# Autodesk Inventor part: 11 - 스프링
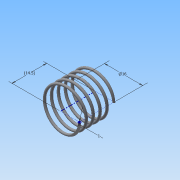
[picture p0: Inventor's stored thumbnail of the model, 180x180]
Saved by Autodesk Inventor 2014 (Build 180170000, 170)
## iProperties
Created: 2015-06
Part Number: 11 - 스프링
Material: 강철, 연강
Document SubType Name: Modeling
Designer: Administrator
Density: 1 g/cm^3
Appearance: 강철
Author: Administrator
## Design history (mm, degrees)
sketch "스케치1"
  geometry: L1 (0, 0)-(8, 0); L2 (8, 0)-(8, 14.5); L3 (8, 14.5)-(0, 14.5); L4 (0, 14.5)-(0, 0); C1 r 0.5 at (8, 0)
  constraints: 8 end point, 2 parallel, 1 centre point, 1 coincident, 1 horizontal, 1 perpendicular
  dimensions: "d0" = 14.5 distance between parallel lines of L1 L3 (derived); "d1" = 16 diameter of L2 L4; "d2" = 1 diameter of C1
feature "코일1" sketch "스케치1" pitch "d3" = 10; turns "d5" = 5; dims "d4" = 14.5 (= d0), "d6" = 0, angle "d7" = 90 deg, angle "d8" = 90 deg, "d9" = 0, "d10" = 0
node "작업 평면1"
sketch "스케치2"
  geometry: L1 (-8.5, 0)-(-7.5, 0) reference; 1 further point
  constraints: 1 horizontal alignment
extrude "돌출1" cut sketch "스케치2" distance "d12" = 10; taper "d13" = 0 deg
node "작업 평면2"
sketch "스케치3"
  geometry: L1 (-7.5, 0)-(-8.5, 0) reference; 1 further point
  constraints: 1 horizontal alignment
extrude "돌출2" cut sketch "스케치3" stored distance "d15" = 10; taper "d16" = 0 deg
node "솔리드1"
node "절단 모서리 투영1"
node "절단 모서리 투영2"
other parameters: "d11" = 0, "d14" = 14.5 (= d0)
